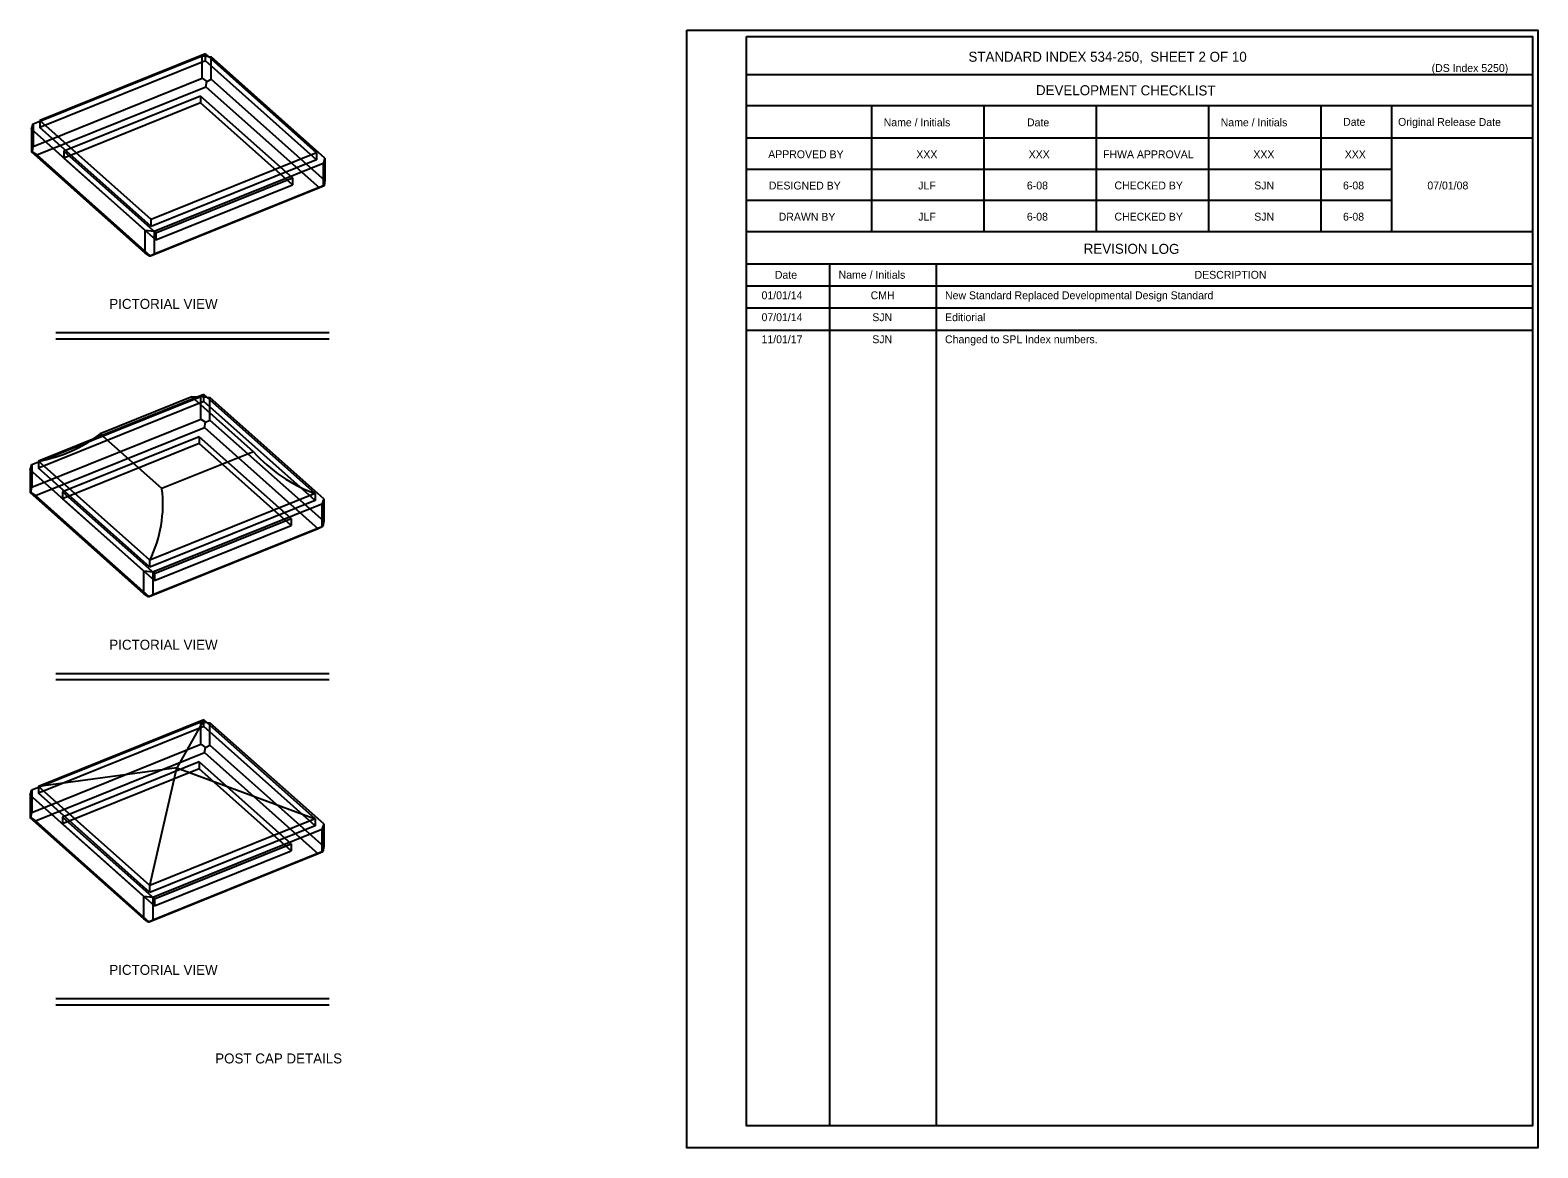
# Model space of a CAD drawing. Extents: x -7.2 to 26.6, y -15.1 to 10.
# Drawn here: x 12.06 to 26.56, y -0.75 to 10 of the extents above; entities that cross this region are included whole.
import ezdxf

# ---------------------------------------------------------------- set-up
doc = ezdxf.new("R2010")
doc.units = 0
for name, color, linetype in [('AdhocPoint_dp', 7, 'Continuous'), ('Patterning', 7, 'Continuous'), ('PlotBorder_dp', 7, 'Continuous'), ('SubStrConc', 7, 'Continuous'), ('TextMisc', 7, 'Continuous')]:
    doc.layers.add(name, color=color, linetype=linetype)

msp = doc.modelspace()

# ---------------------------------------------------------------- linework, layer by layer
at = {"layer": 'Patterning'}
msp.add_line((18.376, -0.75), (18.376, -0.75), dxfattribs=at)
msp.add_lwpolyline([(18.376, 10), (26.556, 10), (26.556, -0.75), (18.376, -0.75)], close=True, dxfattribs=at)
at = {"layer": 'PlotBorder_dp'}
for p, q in [((18.95, 7.328), (26.505, 7.328)), ((18.95, 7.116), (26.505, 7.116)), ((12.31, 7.091), (14.936, 7.091)), ((12.31, 7.031), (14.936, 7.031)), ((12.31, 3.813), (14.936, 3.813)), ((12.31, 3.753), (14.936, 3.753)), ((12.31, 0.685), (14.936, 0.685)), ((12.31, 0.625), (14.936, 0.625))]:
    msp.add_line(p, q, dxfattribs=at)
at = {"layer": 'SubStrConc'}
for p, q in [((13.746, 9.772), (12.155, 9.131)), ((12.155, 9.124), (13.716, 9.754)), ((13.716, 9.537), (13.716, 9.754)), ((13.716, 9.754), (13.803, 9.743)), ((13.746, 9.705), (13.746, 9.772)), ((14.816, 8.819), (13.746, 9.772)), ((13.803, 9.527), (13.803, 9.743)), ((14.896, 8.77), (13.803, 9.743)), ((13.746, 9.705), (12.155, 9.064)), ((14.816, 8.752), (13.746, 9.705)), ((12.092, 8.882), (13.716, 9.537)), ((12.126, 8.801), (13.751, 9.456)), ((13.716, 9.537), (13.76, 9.507)), ((13.751, 9.456), (13.76, 9.507)), ((13.751, 9.456), (14.845, 8.482)), ((13.76, 9.507), (13.803, 9.527)), ((13.803, 9.527), (14.896, 8.553)), ((13.7, 9.366), (12.387, 8.837)), ((13.7, 9.3), (12.387, 8.77)), ((14.584, 8.579), (13.7, 9.366)), ((13.7, 9.366), (13.7, 9.3)), ((14.584, 8.512), (13.7, 9.3)), ((12.075, 9.046), (12.092, 9.098)), ((12.075, 9.046), (12.075, 8.83)), ((13.168, 8.073), (12.075, 9.046)), ((12.092, 9.098), (12.155, 9.124)), ((12.092, 9.098), (12.092, 8.882)), ((12.155, 9.131), (12.155, 9.064)), ((13.225, 8.178), (12.155, 9.131)), ((13.225, 8.111), (12.155, 9.064)), ((12.083, 8.831), (12.092, 8.882)), ((12.075, 8.83), (12.083, 8.831)), ((13.168, 7.856), (12.075, 8.83)), ((12.083, 8.831), (12.126, 8.801)), ((13.22, 7.827), (12.126, 8.801)), ((12.387, 8.837), (12.387, 8.77)), ((12.387, 8.837), (13.271, 8.05)), ((12.387, 8.77), (13.271, 7.983)), ((14.816, 8.819), (13.225, 8.178)), ((14.816, 8.752), (13.225, 8.111)), ((14.879, 8.718), (13.255, 8.063)), ((14.816, 8.819), (14.816, 8.752)), ((14.896, 8.77), (14.879, 8.718)), ((14.879, 8.718), (14.879, 8.501)), ((14.896, 8.77), (14.896, 8.553)), ((13.271, 8.05), (14.584, 8.579)), ((14.584, 8.579), (14.584, 8.512)), ((14.896, 8.553), (14.888, 8.502)), ((14.845, 8.482), (13.22, 7.827)), ((14.879, 8.501), (13.255, 7.846)), ((13.271, 7.983), (14.584, 8.512)), ((14.888, 8.502), (14.845, 8.482)), ((14.888, 8.502), (14.879, 8.501)), ((13.225, 8.111), (13.225, 8.178)), ((13.255, 8.063), (13.168, 8.073)), ((13.168, 7.856), (13.168, 8.073)), ((13.255, 8.063), (13.255, 7.846)), ((13.271, 8.05), (13.271, 7.983)), ((13.211, 7.826), (13.168, 7.856)), ((13.255, 7.846), (13.211, 7.826)), ((13.22, 7.827), (13.211, 7.826)), ((13.733, 6.495), (12.143, 5.854)), ((12.143, 5.847), (13.704, 6.477)), ((13.733, 6.428), (12.143, 5.787)), ((13.617, 6.472), (12.736, 6.117)), ((14.209, 5.945), (13.617, 6.472)), ((13.704, 6.26), (13.704, 6.477)), ((13.704, 6.477), (13.761, 6.47)), ((14.803, 5.542), (13.733, 6.495)), ((13.733, 6.428), (13.733, 6.495)), ((14.803, 5.475), (13.733, 6.428)), ((13.761, 6.47), (13.79, 6.467)), ((13.79, 6.25), (13.79, 6.467)), ((14.884, 5.493), (13.79, 6.467)), ((12.079, 5.605), (13.704, 6.26)), ((13.704, 6.26), (13.747, 6.23)), ((13.747, 6.23), (13.79, 6.25)), ((13.79, 6.25), (14.884, 5.276)), ((12.114, 5.524), (13.739, 6.179)), ((13.688, 6.09), (12.374, 5.56)), ((13.329, 5.59), (12.736, 6.117)), ((14.572, 5.302), (13.688, 6.09)), ((13.688, 6.09), (13.688, 6.023)), ((13.739, 6.179), (13.747, 6.23)), ((13.739, 6.179), (14.832, 5.205)), ((13.688, 6.023), (12.374, 5.493)), ((14.209, 5.945), (13.329, 5.59)), ((14.572, 5.236), (13.688, 6.023)), ((12.062, 5.77), (12.079, 5.822)), ((12.079, 5.822), (12.143, 5.847)), ((12.079, 5.822), (12.079, 5.605)), ((12.143, 5.854), (12.143, 5.787)), ((13.213, 4.901), (12.143, 5.854)), ((12.062, 5.77), (12.062, 5.553)), ((13.155, 4.796), (12.062, 5.77)), ((13.213, 4.834), (12.143, 5.787)), ((12.062, 5.553), (12.07, 5.554)), ((13.155, 4.579), (12.062, 5.553)), ((12.07, 5.554), (12.079, 5.605)), ((12.07, 5.554), (12.114, 5.524)), ((13.207, 4.55), (12.114, 5.524)), ((12.374, 5.56), (12.374, 5.493)), ((12.374, 5.56), (13.258, 4.773)), ((14.803, 5.542), (13.213, 4.901)), ((14.803, 5.542), (14.803, 5.475)), ((12.374, 5.493), (13.258, 4.706)), ((14.803, 5.475), (13.213, 4.834)), ((14.867, 5.441), (13.242, 4.786)), ((14.884, 5.493), (14.867, 5.441)), ((14.867, 5.441), (14.867, 5.224)), ((14.884, 5.493), (14.884, 5.276)), ((14.867, 5.224), (13.242, 4.569)), ((13.258, 4.773), (14.572, 5.302)), ((13.258, 4.706), (14.572, 5.236)), ((14.572, 5.302), (14.572, 5.236)), ((14.875, 5.225), (14.832, 5.205)), ((14.875, 5.225), (14.867, 5.224)), ((14.884, 5.276), (14.875, 5.225)), ((14.832, 5.205), (13.207, 4.55)), ((13.242, 4.786), (13.155, 4.796)), ((13.155, 4.579), (13.155, 4.796)), ((13.213, 4.834), (13.213, 4.901)), ((13.242, 4.786), (13.242, 4.569)), ((13.258, 4.773), (13.258, 4.706)), ((13.199, 4.549), (13.155, 4.579)), ((13.242, 4.569), (13.199, 4.549)), ((13.207, 4.55), (13.199, 4.549)), ((12.079, 2.694), (13.704, 3.349)), ((13.733, 3.367), (12.143, 2.726)), ((13.733, 3.367), (13.473, 2.904)), ((13.704, 3.132), (13.704, 3.349)), ((13.704, 3.349), (13.79, 3.339)), ((14.803, 2.415), (13.733, 3.367)), ((13.733, 3.301), (13.733, 3.367)), ((13.79, 3.122), (13.79, 3.339)), ((14.884, 2.365), (13.79, 3.339)), ((13.733, 3.301), (12.143, 2.66)), ((14.803, 2.348), (13.733, 3.301)), ((12.079, 2.477), (13.704, 3.132)), ((12.114, 2.396), (13.739, 3.051)), ((13.704, 3.132), (13.747, 3.102)), ((13.739, 3.051), (13.747, 3.102)), ((13.739, 3.051), (14.832, 2.078)), ((13.747, 3.102), (13.79, 3.122)), ((13.79, 3.122), (14.884, 2.149)), ((13.473, 2.904), (12.143, 2.726)), ((13.688, 2.962), (12.374, 2.432)), ((13.213, 1.773), (13.473, 2.904)), ((13.473, 2.904), (14.803, 2.415)), ((14.572, 2.175), (13.688, 2.962)), ((13.688, 2.962), (13.688, 2.895)), ((13.688, 2.895), (12.374, 2.366)), ((14.572, 2.108), (13.688, 2.895)), ((12.062, 2.642), (12.079, 2.694)), ((12.062, 2.642), (12.062, 2.425)), ((13.155, 1.668), (12.062, 2.642)), ((12.079, 2.694), (12.079, 2.477)), ((12.143, 2.726), (12.143, 2.66)), ((13.213, 1.773), (12.143, 2.726)), ((13.213, 1.707), (12.143, 2.66)), ((12.07, 2.426), (12.079, 2.477)), ((12.062, 2.425), (12.07, 2.426)), ((13.155, 1.452), (12.062, 2.425)), ((12.07, 2.426), (12.114, 2.396)), ((13.207, 1.422), (12.114, 2.396)), ((12.374, 2.432), (12.374, 2.366)), ((12.374, 2.432), (13.258, 1.645)), ((12.374, 2.366), (13.258, 1.578)), ((14.803, 2.415), (13.213, 1.773)), ((14.803, 2.348), (13.213, 1.707)), ((14.803, 2.415), (14.803, 2.348)), ((14.884, 2.365), (14.867, 2.313)), ((14.884, 2.365), (14.884, 2.149)), ((14.867, 2.313), (13.242, 1.658)), ((13.258, 1.645), (14.572, 2.175)), ((14.572, 2.175), (14.572, 2.108)), ((14.867, 2.313), (14.867, 2.097)), ((14.832, 2.078), (13.207, 1.422)), ((14.867, 2.097), (13.242, 1.441)), ((13.258, 1.578), (14.572, 2.108)), ((14.875, 2.098), (14.832, 2.078)), ((14.875, 2.098), (14.867, 2.097)), ((14.884, 2.149), (14.875, 2.098)), ((13.213, 1.707), (13.213, 1.773)), ((13.242, 1.658), (13.155, 1.668)), ((13.155, 1.452), (13.155, 1.668)), ((13.242, 1.658), (13.242, 1.441)), ((13.258, 1.645), (13.258, 1.578)), ((13.199, 1.421), (13.155, 1.452)), ((13.242, 1.441), (13.199, 1.421)), ((13.207, 1.422), (13.199, 1.421))]:
    msp.add_line(p, q, dxfattribs=at)
for centre, radius, start, end in [((13.618, 6.767), 0.295, 269.614, 292.8049), ((11.879, 7.251), 1.422, 280.6933, 307.1303), ((15.33, 6.959), 1.512, 222.0979, 249.614), ((12.111, 5.441), 1.227, 333.8715, 6.9508)]:
    msp.add_arc(centre, radius, start, end, dxfattribs=at)
at = {"layer": 'TextMisc'}
for p, q in [((26.505, 9.571), (18.95, 9.571)), ((26.505, 9.271), (18.95, 9.271)), ((20.15, 9.271), (20.15, 8.061)), ((21.23, 9.271), (21.23, 8.061)), ((22.31, 9.271), (22.31, 8.061)), ((23.39, 9.271), (23.39, 8.061)), ((24.47, 9.271), (24.47, 8.061)), ((25.15, 9.271), (25.15, 8.061)), ((26.505, 8.961), (18.95, 8.961)), ((25.15, 8.661), (18.95, 8.661)), ((25.15, 8.361), (18.95, 8.361)), ((26.505, 8.061), (18.95, 8.061)), ((26.505, 7.75), (18.95, 7.75)), ((19.745, 7.75), (19.745, -0.539)), ((20.773, 7.75), (20.773, -0.539)), ((26.505, 7.539), (18.95, 7.539))]:
    msp.add_line(p, q, dxfattribs=at)
msp.add_lwpolyline([(18.95, 9.939), (26.505, 9.939), (26.505, -0.539), (18.95, -0.539)], close=True, dxfattribs=at)

# ---------------------------------------------------------------- texts
at = {"layer": 'AdhocPoint_dp'}
for s, height, p in [('STANDARD INDEX 534-250,  SHEET 2 OF 10', 0.096, (21.082, 9.696)), ('XXX', 0.0756, (20.581, 8.768)), ('XXX', 0.0756, (21.661, 8.768)), ('XXX', 0.0756, (23.821, 8.768)), ('XXX', 0.0756, (24.7, 8.768)), ('JLF', 0.0756, (20.6, 8.468)), ('6-08', 0.0756, (21.644, 8.468)), ('SJN', 0.0756, (23.83, 8.468)), ('6-08', 0.0756, (24.683, 8.468)), ('07/01/08', 0.0756, (25.494, 8.468)), ('JLF', 0.0756, (20.6, 8.168)), ('6-08', 0.0756, (21.644, 8.168)), ('SJN', 0.0756, (23.83, 8.168)), ('6-08', 0.0756, (24.683, 8.168)), ('DESCRIPTION', 0.0756, (23.256, 7.609)), ('PICTORIAL VIEW', 0.096, (12.823, 7.319)), ('01/01/14', 0.0756, (19.093, 7.412)), ('CMH', 0.0756, (20.142, 7.412)), ('New Standard Replaced Developmental Design Standard', 0.0756, (20.857, 7.412)), ('07/01/14', 0.0756, (19.093, 7.201)), ('SJN', 0.0756, (20.158, 7.201)), ('Editiorial', 0.0756, (20.857, 7.201)), ('11/01/17', 0.0756, (19.093, 6.989)), ('SJN', 0.0756, (20.158, 6.989)), ('Changed to SPL Index numbers.', 0.0756, (20.857, 6.989)), ('PICTORIAL VIEW', 0.096, (12.823, 4.041)), ('PICTORIAL VIEW', 0.096, (12.823, 0.914)), ('POST CAP DETAILS', 0.096, (13.841, 0.062))]:
    msp.add_text(s, height=height, dxfattribs=at).set_placement(p)
for s, height, p in [('DEVELOPMENT CHECKLIST', 0.096, (21.731, 9.375)), ('Name / Initials', 0.0756, (20.267, 9.076)), ('Date', 0.0756, (21.645, 9.075)), ('Name / Initials', 0.0756, (23.507, 9.076)), ('Date', 0.0756, (24.684, 9.08)), ('Original Release Date', 0.0756, (25.212, 9.08)), ('APPROVED BY', 0.0756, (19.157, 8.769)), ('FHWA APPROVAL', 0.0756, (22.376, 8.769)), ('DESIGNED BY', 0.0756, (19.163, 8.468)), ('CHECKED BY', 0.0756, (22.486, 8.469)), ('DRAWN BY', 0.0756, (19.258, 8.168)), ('CHECKED BY', 0.0756, (22.486, 8.169)), ('REVISION LOG', 0.096, (22.19, 7.85)), ('Date', 0.0756, (19.221, 7.609)), ('Name / Initials', 0.0756, (19.834, 7.61))]:
    msp.add_text(s, height=height, rotation=359.8756, dxfattribs=at).set_placement(p)
at = {"layer": 'PlotBorder_dp'}
msp.add_text('(DS Index 5250)', height=0.0756, dxfattribs=at).set_placement((25.535, 9.598))

doc.saveas('drawing.dxf')
